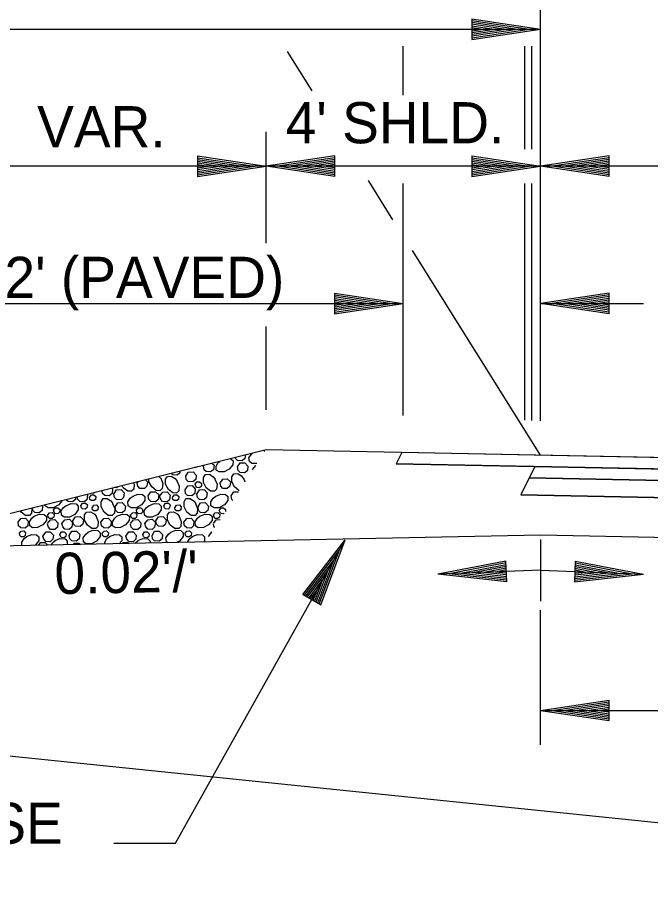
# Model space of a CAD drawing. Extents: x 2478 to 3210, y 439 to 841.
# Drawn here: x 2590.31 to 2608.74, y 577.82 to 603.61 of the extents above; entities that cross this region are included whole.
import ezdxf

# ---------------------------------------------------------------- set-up
doc = ezdxf.new("R2010")
doc.units = 0
for name, color, linetype in [('19', 7, 'Continuous'), ('R_Annotation', 7, 'Continuous'), ('R_Dimension', 7, 'Continuous'), ('R_Exist Surface', 7, 'Continuous')]:
    doc.layers.add(name, color=color, linetype=linetype)

msp = doc.modelspace()

# ---------------------------------------------------------------- linework, layer by layer
at = {"layer": '19'}
for points in [[(2601.503, 590.935), (2601.338, 590.605), (2605.378, 590.524), (2627.711, 590.078), (2649.713, 589.634), (2653.713, 589.474), (2653.543, 589.814), (2649.543, 589.974), (2627.543, 590.414)], [(2605.378, 590.524), (2605.212, 590.194), (2649.879, 589.301), (2649.713, 589.634)], [(2605.212, 590.194), (2604.965, 589.699), (2650.132, 588.796), (2649.879, 589.301)]]:
    msp.add_lwpolyline(points, close=True, dxfattribs=at)
at = {"layer": 'R_Annotation'}
for p, q in [((2597.543, 591.014), (2577.543, 586.014)), ((2627.543, 590.414), (2597.543, 591.014)), ((2601.503, 590.935), (2601.338, 590.605)), ((2627.711, 590.078), (2601.338, 590.605)), ((2605.378, 590.524), (2604.965, 589.699)), ((2627.879, 589.741), (2605.212, 590.194)), ((2628.132, 589.236), (2604.965, 589.699)), ((2605.543, 588.52), (2586.003, 588.129)), ((2666.995, 587.291), (2605.543, 588.52))]:
    msp.add_line(p, q, dxfattribs=at)
at = {"layer": 'R_Dimension'}
for p, q in [((2605.543, 599.281), (2605.543, 604.281)), ((2603.543, 603.581), (2605.543, 603.281)), ((2603.543, 603.581), (2603.543, 602.981)), ((2603.543, 603.531), (2605.209, 603.281)), ((2603.543, 603.48), (2604.865, 603.281)), ((2603.543, 603.43), (2604.532, 603.281)), ((2603.543, 603.378), (2604.193, 603.281)), ((2577.543, 603.281), (2605.543, 603.281)), ((2603.543, 603.328), (2603.859, 603.281)), ((2603.543, 602.981), (2605.543, 603.281)), ((2603.543, 603.183), (2604.193, 603.281)), ((2603.543, 603.082), (2604.865, 603.281)), ((2603.543, 603.031), (2605.209, 603.281)), ((2603.543, 603.132), (2604.532, 603.281)), ((2603.543, 603.234), (2603.859, 603.281)), ((2598.891, 601.477), (2598.169, 602.629)), ((2601.539, 601.351), (2601.539, 602.781)), ((2605.08, 599.781), (2605.08, 602.781)), ((2605.29, 599.781), (2605.29, 602.781)), ((2597.543, 597.038), (2597.543, 600.281)), ((2595.543, 599.581), (2597.543, 599.281)), ((2595.543, 599.581), (2595.543, 598.981)), ((2595.543, 599.531), (2597.209, 599.281)), ((2595.543, 599.48), (2596.865, 599.281)), ((2599.543, 599.581), (2597.543, 599.281)), ((2599.543, 599.531), (2597.877, 599.281)), ((2599.543, 599.48), (2598.221, 599.281)), ((2599.543, 598.981), (2599.543, 599.581)), ((2603.543, 599.581), (2605.543, 599.281)), ((2603.543, 599.581), (2603.543, 598.981)), ((2603.543, 599.531), (2605.209, 599.281)), ((2603.543, 599.48), (2604.865, 599.281)), ((2607.543, 599.581), (2605.543, 599.281)), ((2607.543, 599.531), (2605.877, 599.281)), ((2607.543, 599.48), (2606.221, 599.281)), ((2607.543, 598.981), (2607.543, 599.581)), ((2666.995, 599.281), (2586.003, 599.281)), ((2595.543, 599.43), (2596.532, 599.281)), ((2595.543, 599.378), (2596.193, 599.281)), ((2595.543, 599.328), (2595.859, 599.281)), ((2595.543, 598.981), (2597.543, 599.281)), ((2595.543, 599.183), (2596.193, 599.281)), ((2595.543, 599.082), (2596.865, 599.281)), ((2595.543, 599.031), (2597.209, 599.281)), ((2595.543, 599.132), (2596.532, 599.281)), ((2595.543, 599.234), (2595.859, 599.281)), ((2599.543, 598.981), (2597.543, 599.281)), ((2599.543, 599.031), (2597.877, 599.281)), ((2599.543, 599.082), (2598.221, 599.281)), ((2599.543, 599.43), (2598.554, 599.281)), ((2599.543, 599.132), (2598.554, 599.281)), ((2599.543, 599.379), (2598.893, 599.281)), ((2599.543, 599.184), (2598.893, 599.281)), ((2599.543, 599.328), (2599.227, 599.281)), ((2599.543, 599.234), (2599.227, 599.281)), ((2603.543, 599.43), (2604.532, 599.281)), ((2603.543, 599.378), (2604.193, 599.281)), ((2603.543, 599.328), (2603.859, 599.281)), ((2603.543, 598.981), (2605.543, 599.281)), ((2603.543, 599.183), (2604.193, 599.281)), ((2603.543, 599.082), (2604.865, 599.281)), ((2603.543, 599.031), (2605.209, 599.281)), ((2603.543, 599.132), (2604.532, 599.281)), ((2603.543, 599.234), (2603.859, 599.281)), ((2605.543, 591.855), (2605.543, 599.281)), ((2607.543, 598.981), (2605.543, 599.281)), ((2607.543, 599.031), (2605.877, 599.281)), ((2607.543, 599.082), (2606.221, 599.281)), ((2607.543, 599.43), (2606.554, 599.281)), ((2607.543, 599.132), (2606.554, 599.281)), ((2607.543, 599.379), (2606.893, 599.281)), ((2607.543, 599.184), (2606.893, 599.281)), ((2607.543, 599.328), (2607.227, 599.281)), ((2607.543, 599.234), (2607.227, 599.281)), ((2601.242, 597.722), (2600.528, 598.862)), ((2601.539, 592.015), (2601.539, 598.781)), ((2605.08, 591.874), (2605.08, 598.781)), ((2605.29, 591.865), (2605.29, 598.781)), ((2605.543, 590.854), (2601.806, 596.822)), ((2599.539, 595.581), (2601.539, 595.281)), ((2599.539, 595.581), (2599.539, 594.981)), ((2599.539, 595.531), (2601.205, 595.281)), ((2599.539, 595.48), (2600.861, 595.281)), ((2599.539, 595.43), (2600.528, 595.281)), ((2599.539, 595.378), (2600.189, 595.281)), ((2607.543, 595.581), (2605.543, 595.281)), ((2607.543, 595.531), (2605.877, 595.281)), ((2607.543, 595.48), (2606.221, 595.281)), ((2607.543, 595.43), (2606.554, 595.281)), ((2607.543, 595.379), (2606.893, 595.281)), ((2607.543, 594.981), (2607.543, 595.581)), ((2588.615, 595.281), (2601.539, 595.281)), ((2599.539, 595.328), (2599.855, 595.281)), ((2599.539, 594.981), (2601.539, 595.281)), ((2599.539, 595.183), (2600.189, 595.281)), ((2599.539, 595.082), (2600.861, 595.281)), ((2599.539, 595.031), (2601.205, 595.281)), ((2599.539, 595.132), (2600.528, 595.281)), ((2599.539, 595.234), (2599.855, 595.281)), ((2607.543, 594.981), (2605.543, 595.281)), ((2605.543, 595.281), (2608.543, 595.281)), ((2607.543, 595.031), (2605.877, 595.281)), ((2607.543, 595.082), (2606.221, 595.281)), ((2607.543, 595.132), (2606.554, 595.281)), ((2607.543, 595.184), (2606.893, 595.281)), ((2607.543, 595.328), (2607.227, 595.281)), ((2607.543, 595.234), (2607.227, 595.281)), ((2597.543, 592.175), (2597.543, 594.607)), ((2597.475, 590.997), (2597.51, 590.965)), ((2595.723, 590.534), (2595.745, 590.565)), ((2594.424, 590.235), (2594.473, 590.174)), ((2596.888, 590.184), (2596.928, 590.08)), ((2597.156, 590.427), (2597.153, 590.439)), ((2593.788, 590.044), (2593.814, 590.082)), ((2595.877, 588.483), (2595.873, 588.494)), ((2598.613, 586.79), (2599.851, 588.389)), ((2599.136, 586.497), (2599.851, 588.389)), ((2605.543, 588.402), (2605.543, 586.604)), ((2598.656, 586.766), (2599.688, 588.098)), ((2599.093, 586.522), (2599.688, 588.098)), ((2598.701, 586.741), (2599.52, 587.798)), ((2599.048, 586.547), (2599.52, 587.798)), ((2604.531, 587.763), (2602.545, 587.383)), ((2604.533, 587.713), (2602.879, 587.396)), ((2604.535, 587.662), (2603.222, 587.41)), ((2604.537, 587.612), (2603.555, 587.423)), ((2604.555, 587.163), (2604.531, 587.763)), ((2606.553, 587.763), (2606.53, 587.163)), ((2606.547, 587.612), (2607.53, 587.424)), ((2606.549, 587.662), (2607.862, 587.41)), ((2606.551, 587.713), (2608.206, 587.397)), ((2606.553, 587.763), (2608.54, 587.383)), ((2598.744, 586.717), (2599.357, 587.507)), ((2599.004, 586.571), (2599.357, 587.507)), ((2605.543, 587.503), (2602.545, 587.383)), ((2604.555, 587.163), (2602.545, 587.383)), ((2604.553, 587.213), (2602.879, 587.396)), ((2604.551, 587.264), (2603.222, 587.41)), ((2604.549, 587.314), (2603.555, 587.423)), ((2604.539, 587.561), (2603.894, 587.437)), ((2604.547, 587.366), (2603.894, 587.437)), ((2604.542, 587.51), (2604.228, 587.45)), ((2604.545, 587.416), (2604.228, 587.45)), ((2605.543, 587.503), (2608.54, 587.383)), ((2606.53, 587.163), (2608.54, 587.383)), ((2606.532, 587.213), (2608.206, 587.397)), ((2606.534, 587.264), (2607.862, 587.41)), ((2606.536, 587.314), (2607.53, 587.424)), ((2606.538, 587.365), (2607.191, 587.437)), ((2606.54, 587.416), (2606.857, 587.45)), ((2606.543, 587.51), (2606.857, 587.45)), ((2606.545, 587.56), (2607.191, 587.437)), ((2598.79, 586.691), (2599.192, 587.211)), ((2598.96, 586.596), (2599.192, 587.211)), ((2598.833, 586.667), (2599.029, 586.92)), ((2598.915, 586.621), (2599.029, 586.92)), ((2598.613, 586.79), (2599.136, 586.497)), ((2605.543, 582.406), (2605.543, 586.336)), ((2607.543, 583.706), (2605.543, 583.406)), ((2607.543, 583.656), (2605.877, 583.406)), ((2607.543, 583.605), (2606.221, 583.406)), ((2607.543, 583.555), (2606.554, 583.406)), ((2607.543, 583.504), (2606.893, 583.406)), ((2607.543, 583.106), (2607.543, 583.706)), ((2607.543, 583.106), (2605.543, 583.406)), ((2649.543, 583.406), (2605.543, 583.406)), ((2607.543, 583.156), (2605.877, 583.406)), ((2607.543, 583.207), (2606.221, 583.406)), ((2607.543, 583.257), (2606.554, 583.406)), ((2607.543, 583.309), (2606.893, 583.406)), ((2607.543, 583.453), (2607.227, 583.406)), ((2607.543, 583.359), (2607.227, 583.406))]:
    msp.add_line(p, q, dxfattribs=at)
for points in [[(2596.506, 590.755), (2596.518, 590.754), (2596.583, 590.689), (2596.578, 590.574), (2596.473, 590.444), (2596.323, 590.369), (2596.173, 590.369), (2596.093, 590.424), (2596.088, 590.539), (2596.153, 590.644), (2596.193, 590.677)], [(2596.94, 590.864), (2596.928, 590.759), (2596.843, 590.694), (2596.713, 590.699), (2596.653, 590.759), (2596.648, 590.791)], [(2597.279, 590.614), (2597.133, 590.614), (2597.058, 590.674), (2597.043, 590.784), (2597.118, 590.889), (2597.145, 590.915)], [(2595.521, 590.509), (2595.493, 590.494), (2595.458, 590.493)], [(2595.968, 590.621), (2596.028, 590.564), (2596.013, 590.434), (2595.928, 590.369), (2595.803, 590.379), (2595.743, 590.434), (2595.723, 590.534)], [(2596.713, 590.514), (2596.793, 590.629), (2596.923, 590.634), (2597.013, 590.539), (2597.003, 590.409), (2596.923, 590.339), (2596.793, 590.354), (2596.733, 590.414), (2596.713, 590.514)], [(2597.153, 590.439), (2597.243, 590.559), (2597.243, 590.559)], [(2594.473, 590.184), (2594.533, 590.029), (2594.518, 589.889), (2594.453, 589.819), (2594.338, 589.829), (2594.213, 589.929), (2594.128, 590.084), (2594.128, 590.161)], [(2594.948, 590.109), (2595.008, 589.954), (2594.998, 589.814), (2594.938, 589.749), (2594.823, 589.754), (2594.698, 589.854), (2594.613, 590.009), (2594.613, 590.154), (2594.668, 590.234), (2594.783, 590.249), (2594.893, 590.174), (2594.953, 590.099)], [(2595.036, 590.388), (2595.033, 590.339), (2594.953, 590.274), (2594.823, 590.279), (2594.779, 590.323)], [(2595.203, 590.249), (2595.278, 590.359), (2595.418, 590.369), (2595.503, 590.274), (2595.493, 590.144), (2595.408, 590.079), (2595.278, 590.089), (2595.218, 590.144), (2595.203, 590.249)], [(2596.053, 590.159), (2596.118, 590.009), (2596.103, 589.869), (2596.038, 589.804), (2595.928, 589.809), (2595.798, 589.904), (2595.723, 590.059), (2595.718, 590.209), (2595.783, 590.294), (2595.893, 590.299), (2596.003, 590.229), (2596.063, 590.154)], [(2596.762, 589.829), (2596.753, 589.829), (2596.628, 589.929), (2596.543, 590.084), (2596.543, 590.229), (2596.603, 590.314), (2596.723, 590.319), (2596.823, 590.254), (2596.888, 590.174)], [(2593.227, 589.936), (2593.193, 589.904), (2593.133, 589.912)], [(2593.685, 590.05), (2593.703, 590.009), (2593.688, 589.869), (2593.623, 589.804), (2593.513, 589.809), (2593.383, 589.904), (2593.352, 589.967)], [(2594.032, 590.137), (2594.093, 590.079), (2594.073, 589.949), (2593.998, 589.884), (2593.868, 589.889), (2593.808, 589.949), (2593.788, 590.044)], [(2595.183, 589.844), (2595.263, 589.964), (2595.388, 589.969), (2595.483, 589.869), (2595.473, 589.744), (2595.383, 589.674), (2595.258, 589.679), (2595.198, 589.744), (2595.183, 589.844)], [(2595.483, 590.009), (2595.528, 590.079), (2595.608, 590.084), (2595.663, 590.029), (2595.658, 589.949), (2595.608, 589.904), (2595.528, 589.914), (2595.493, 589.949), (2595.483, 590.009)], [(2596.203, 590.044), (2596.283, 590.159), (2596.413, 590.169), (2596.508, 590.079), (2596.488, 589.949), (2596.413, 589.884), (2596.283, 589.889), (2596.223, 589.949), (2596.203, 590.044)], [(2592.323, 589.709), (2592.338, 589.694), (2592.318, 589.559), (2592.243, 589.494), (2592.113, 589.504), (2592.058, 589.564), (2592.036, 589.638)], [(2592.403, 589.624), (2592.458, 589.699), (2592.528, 589.699), (2592.583, 589.649), (2592.578, 589.564), (2592.528, 589.534), (2592.448, 589.539), (2592.413, 589.564), (2592.403, 589.624)], [(2592.535, 589.762), (2592.523, 589.749), (2592.489, 589.751)], [(2593.047, 589.891), (2593.068, 589.869), (2593.058, 589.744), (2592.968, 589.674), (2592.843, 589.679), (2592.783, 589.744), (2592.771, 589.821)], [(2593.108, 589.724), (2593.188, 589.844), (2593.323, 589.854), (2593.408, 589.754), (2593.393, 589.624), (2593.318, 589.559), (2593.188, 589.564), (2593.128, 589.624), (2593.108, 589.724)], [(2593.663, 589.659), (2593.813, 589.719), (2593.948, 589.709), (2594.013, 589.649), (2594.013, 589.534), (2593.918, 589.404), (2593.758, 589.324), (2593.613, 589.324), (2593.523, 589.379), (2593.518, 589.494), (2593.588, 589.604), (2593.668, 589.664)], [(2594.113, 589.669), (2594.188, 589.784), (2594.323, 589.789), (2594.418, 589.699), (2594.403, 589.564), (2594.318, 589.499), (2594.188, 589.509), (2594.128, 589.564), (2594.113, 589.669)], [(2594.443, 589.664), (2594.533, 589.779), (2594.658, 589.789), (2594.753, 589.694), (2594.733, 589.559), (2594.658, 589.494), (2594.528, 589.504), (2594.473, 589.564), (2594.443, 589.664)], [(2594.818, 589.624), (2594.873, 589.699), (2594.943, 589.699), (2594.998, 589.649), (2594.993, 589.564), (2594.943, 589.534), (2594.863, 589.539), (2594.828, 589.564), (2594.818, 589.624)], [(2595.523, 589.724), (2595.603, 589.844), (2595.738, 589.854), (2595.823, 589.754), (2595.808, 589.624), (2595.733, 589.559), (2595.603, 589.564), (2595.543, 589.624), (2595.523, 589.724)], [(2596.078, 589.659), (2596.228, 589.719), (2596.363, 589.709), (2596.428, 589.649), (2596.428, 589.534), (2596.333, 589.404), (2596.173, 589.324), (2596.028, 589.324), (2595.938, 589.379), (2595.933, 589.494), (2596.003, 589.604), (2596.083, 589.664)], [(2596.528, 589.669), (2596.603, 589.784), (2596.736, 589.789)], [(2596.571, 589.538), (2596.543, 589.564), (2596.528, 589.669)], [(2591.592, 589.527), (2591.503, 589.404), (2591.343, 589.324), (2591.198, 589.324), (2591.108, 589.379), (2591.106, 589.405)], [(2591.713, 589.384), (2591.868, 589.444), (2592.008, 589.434), (2592.073, 589.374), (2592.073, 589.259), (2591.973, 589.129), (2591.813, 589.054), (2591.663, 589.049), (2591.583, 589.109), (2591.578, 589.229), (2591.643, 589.329), (2591.723, 589.389)], [(2591.995, 589.627), (2591.988, 589.564), (2591.903, 589.499), (2591.773, 589.509), (2591.719, 589.558)], [(2592.148, 589.384), (2592.198, 589.454), (2592.283, 589.454), (2592.338, 589.404), (2592.318, 589.324), (2592.273, 589.284), (2592.198, 589.289), (2592.168, 589.324), (2592.148, 589.384)], [(2593.073, 589.449), (2593.133, 589.304), (2593.123, 589.164), (2593.063, 589.094), (2592.948, 589.094), (2592.823, 589.199), (2592.738, 589.354), (2592.738, 589.499), (2592.793, 589.589), (2592.913, 589.594), (2593.018, 589.529), (2593.078, 589.444)], [(2593.148, 589.349), (2593.223, 589.464), (2593.353, 589.474), (2593.448, 589.374), (2593.433, 589.244), (2593.348, 589.179), (2593.223, 589.184), (2593.163, 589.244), (2593.148, 589.349)], [(2594.128, 589.384), (2594.283, 589.444), (2594.423, 589.434), (2594.488, 589.374), (2594.488, 589.259), (2594.388, 589.129), (2594.228, 589.054), (2594.078, 589.049), (2593.998, 589.109), (2593.993, 589.229), (2594.058, 589.329), (2594.138, 589.389)], [(2594.563, 589.384), (2594.613, 589.454), (2594.698, 589.454), (2594.753, 589.404), (2594.733, 589.324), (2594.688, 589.284), (2594.613, 589.289), (2594.583, 589.324), (2594.563, 589.384)], [(2595.488, 589.449), (2595.548, 589.304), (2595.538, 589.164), (2595.478, 589.094), (2595.363, 589.094), (2595.238, 589.199), (2595.153, 589.354), (2595.153, 589.499), (2595.208, 589.589), (2595.328, 589.594), (2595.433, 589.529), (2595.493, 589.444)], [(2595.563, 589.349), (2595.638, 589.464), (2595.768, 589.474), (2595.863, 589.374), (2595.848, 589.244), (2595.763, 589.179), (2595.638, 589.184), (2595.578, 589.244), (2595.563, 589.349)], [(2590.716, 589.308), (2590.718, 589.304), (2590.708, 589.164), (2590.648, 589.094), (2590.533, 589.094), (2590.408, 589.199), (2590.393, 589.227)], [(2591.023, 589.384), (2591.033, 589.374), (2591.018, 589.244), (2590.933, 589.179), (2590.808, 589.184), (2590.748, 589.244), (2590.738, 589.313)], [(2591.183, 589.114), (2591.233, 589.179), (2591.313, 589.184), (2591.368, 589.129), (2591.358, 589.049), (2591.313, 589.009), (2591.233, 589.014), (2591.198, 589.054), (2591.183, 589.114)], [(2591.353, 589.254), (2591.403, 589.319), (2591.478, 589.324), (2591.533, 589.269), (2591.528, 589.194), (2591.478, 589.149), (2591.403, 589.159), (2591.368, 589.194), (2591.353, 589.254)], [(2592.593, 589.069), (2592.653, 588.924), (2592.643, 588.779), (2592.583, 588.714), (2592.468, 588.714), (2592.338, 588.819), (2592.258, 588.964), (2592.253, 589.119), (2592.313, 589.199), (2592.428, 589.209), (2592.538, 589.144), (2592.603, 589.064)], [(2592.473, 589.324), (2592.523, 589.399), (2592.603, 589.404), (2592.653, 589.349), (2592.643, 589.264), (2592.593, 589.229), (2592.523, 589.234), (2592.483, 589.264), (2592.473, 589.324)], [(2593.598, 589.114), (2593.648, 589.179), (2593.728, 589.184), (2593.783, 589.129), (2593.773, 589.049), (2593.728, 589.009), (2593.648, 589.014), (2593.613, 589.054), (2593.598, 589.114)], [(2593.768, 589.254), (2593.818, 589.319), (2593.893, 589.324), (2593.948, 589.269), (2593.943, 589.194), (2593.893, 589.149), (2593.818, 589.159), (2593.783, 589.194), (2593.768, 589.254)], [(2595.008, 589.069), (2595.068, 588.924), (2595.058, 588.779), (2594.998, 588.714), (2594.883, 588.714), (2594.753, 588.819), (2594.673, 588.964), (2594.668, 589.119), (2594.728, 589.199), (2594.843, 589.209), (2594.953, 589.144), (2595.018, 589.064)], [(2594.888, 589.324), (2594.938, 589.399), (2595.018, 589.404), (2595.068, 589.349), (2595.058, 589.264), (2595.008, 589.229), (2594.938, 589.234), (2594.898, 589.264), (2594.888, 589.324)], [(2596.013, 589.114), (2596.063, 589.179), (2596.143, 589.184), (2596.198, 589.129), (2596.188, 589.049), (2596.143, 589.009), (2596.063, 589.014), (2596.028, 589.054), (2596.013, 589.114)], [(2596.183, 589.254), (2596.233, 589.319), (2596.308, 589.324), (2596.363, 589.269), (2596.359, 589.216)], [(2596.327, 589.166), (2596.308, 589.149), (2596.233, 589.159), (2596.198, 589.194), (2596.183, 589.254)], [(2590.318, 588.899), (2590.403, 589.014), (2590.533, 589.019), (2590.613, 588.929), (2590.603, 588.799), (2590.528, 588.729), (2590.403, 588.739), (2590.333, 588.799), (2590.318, 588.899)], [(2590.783, 589.074), (2590.933, 589.134), (2591.078, 589.124), (2591.148, 589.064), (2591.143, 588.949), (2591.038, 588.824), (2590.888, 588.744), (2590.738, 588.739), (2590.658, 588.799), (2590.653, 588.914), (2590.718, 589.019), (2590.793, 589.084)], [(2591.178, 588.864), (2591.263, 588.974), (2591.393, 588.984), (2591.478, 588.884), (2591.468, 588.759), (2591.393, 588.689), (2591.263, 588.694), (2591.203, 588.759), (2591.178, 588.849)], [(2591.598, 588.864), (2591.683, 588.974), (2591.813, 588.989), (2591.903, 588.889), (2591.883, 588.759), (2591.808, 588.694), (2591.683, 588.704), (2591.623, 588.764), (2591.598, 588.864)], [(2591.918, 588.944), (2591.993, 589.059), (2592.128, 589.069), (2592.223, 588.974), (2592.203, 588.844), (2592.123, 588.779), (2591.993, 588.784), (2591.933, 588.844), (2591.918, 588.944)], [(2592.733, 588.899), (2592.818, 589.014), (2592.948, 589.019), (2593.028, 588.929), (2593.018, 588.799), (2592.943, 588.729), (2592.818, 588.739), (2592.748, 588.799), (2592.733, 588.899)], [(2593.198, 589.074), (2593.348, 589.134), (2593.493, 589.124), (2593.563, 589.064), (2593.558, 588.949), (2593.453, 588.824), (2593.303, 588.744), (2593.153, 588.739), (2593.073, 588.799), (2593.068, 588.914), (2593.133, 589.019), (2593.208, 589.084)], [(2593.593, 588.864), (2593.678, 588.974), (2593.808, 588.984), (2593.893, 588.884), (2593.883, 588.759), (2593.808, 588.689), (2593.678, 588.694), (2593.618, 588.759), (2593.593, 588.849)], [(2594.013, 588.864), (2594.098, 588.974), (2594.228, 588.989), (2594.318, 588.889), (2594.298, 588.759), (2594.223, 588.694), (2594.098, 588.704), (2594.038, 588.764), (2594.013, 588.864)], [(2594.333, 588.944), (2594.408, 589.059), (2594.543, 589.069), (2594.638, 588.974), (2594.618, 588.844), (2594.538, 588.779), (2594.408, 588.784), (2594.348, 588.844), (2594.333, 588.944)], [(2595.148, 588.899), (2595.233, 589.014), (2595.363, 589.019), (2595.443, 588.929), (2595.433, 588.799), (2595.358, 588.729), (2595.233, 588.739), (2595.163, 588.799), (2595.148, 588.899)], [(2595.613, 589.074), (2595.763, 589.134), (2595.908, 589.124), (2595.978, 589.064), (2595.973, 588.949), (2595.868, 588.824), (2595.718, 588.744), (2595.568, 588.739), (2595.488, 588.799), (2595.483, 588.914), (2595.548, 589.019), (2595.623, 589.084)], [(2596.008, 588.864), (2596.093, 588.974), (2596.206, 588.983)], [(2590.358, 588.579), (2590.408, 588.644), (2590.483, 588.649), (2590.538, 588.594), (2590.528, 588.519), (2590.483, 588.474), (2590.408, 588.479), (2590.368, 588.519), (2590.358, 588.579)], [(2591.808, 588.519), (2591.883, 588.639), (2592.018, 588.644), (2592.113, 588.544), (2592.098, 588.419), (2592.013, 588.354), (2591.883, 588.359), (2591.823, 588.419), (2591.808, 588.519)], [(2592.353, 588.614), (2592.503, 588.674), (2592.643, 588.659), (2592.713, 588.594), (2592.713, 588.484), (2592.608, 588.354), (2592.458, 588.274), (2592.303, 588.274), (2592.228, 588.334), (2592.213, 588.444), (2592.288, 588.549), (2592.358, 588.614)], [(2592.773, 588.579), (2592.823, 588.644), (2592.898, 588.649), (2592.953, 588.594), (2592.943, 588.519), (2592.898, 588.474), (2592.823, 588.479), (2592.783, 588.519), (2592.773, 588.579)], [(2594.223, 588.519), (2594.298, 588.639), (2594.433, 588.644), (2594.528, 588.544), (2594.513, 588.419), (2594.428, 588.354), (2594.298, 588.359), (2594.238, 588.419), (2594.223, 588.519)], [(2594.768, 588.614), (2594.918, 588.674), (2595.058, 588.659), (2595.128, 588.594), (2595.128, 588.484), (2595.023, 588.354), (2594.936, 588.308)], [(2595.188, 588.579), (2595.238, 588.644), (2595.313, 588.649), (2595.368, 588.594), (2595.358, 588.519), (2595.313, 588.474), (2595.238, 588.479), (2595.198, 588.519), (2595.188, 588.579)], [(2596.048, 588.743), (2596.033, 588.759), (2596.008, 588.849)], [(2590.432, 588.218), (2590.428, 588.319), (2590.493, 588.429), (2590.573, 588.489)], [(2590.563, 588.484), (2590.718, 588.544), (2590.858, 588.534), (2590.923, 588.474), (2590.923, 588.359), (2590.818, 588.234), (2590.8, 588.225)], [(2591.043, 588.494), (2591.133, 588.619), (2591.258, 588.624), (2591.348, 588.529), (2591.333, 588.404), (2591.258, 588.334), (2591.128, 588.344), (2591.073, 588.404), (2591.043, 588.494)], [(2591.393, 588.364), (2591.543, 588.424), (2591.688, 588.414), (2591.753, 588.349), (2591.748, 588.244)], [(2591.538, 588.544), (2591.588, 588.619), (2591.663, 588.624), (2591.723, 588.564), (2591.713, 588.484), (2591.663, 588.444), (2591.588, 588.459), (2591.553, 588.484), (2591.538, 588.544)], [(2592.845, 588.266), (2592.843, 588.319), (2592.908, 588.429), (2592.988, 588.489)], [(2592.978, 588.484), (2593.133, 588.544), (2593.273, 588.534), (2593.338, 588.474), (2593.338, 588.359), (2593.266, 588.275)], [(2593.105, 579.543), (2594.903, 579.543), (2599.851, 588.389)], [(2593.458, 588.494), (2593.548, 588.619), (2593.673, 588.624), (2593.763, 588.529), (2593.748, 588.404), (2593.673, 588.334), (2593.543, 588.344), (2593.488, 588.404), (2593.458, 588.494)], [(2593.808, 588.364), (2593.958, 588.424), (2594.103, 588.414), (2594.168, 588.349), (2594.165, 588.293)], [(2593.953, 588.544), (2594.003, 588.619), (2594.078, 588.624), (2594.138, 588.564), (2594.128, 588.484), (2594.078, 588.444), (2594.003, 588.459), (2593.968, 588.484), (2593.953, 588.544)], [(2594.682, 588.303), (2594.643, 588.334), (2594.628, 588.444), (2594.703, 588.549), (2594.773, 588.614)], [(2595.258, 588.315), (2595.258, 588.319), (2595.323, 588.429), (2595.403, 588.489)], [(2595.393, 588.484), (2595.548, 588.544), (2595.688, 588.534), (2595.753, 588.474), (2595.753, 588.359), (2595.723, 588.324)], [(2595.873, 588.494), (2595.963, 588.619), (2595.967, 588.62)], [(2590.917, 588.228), (2590.978, 588.309), (2591.103, 588.314), (2591.188, 588.233)], [(2591.28, 588.235), (2591.323, 588.304), (2591.398, 588.364)], [(2591.934, 588.248), (2591.963, 588.289), (2592.093, 588.294), (2592.133, 588.252)], [(2593.368, 588.277), (2593.393, 588.309), (2593.518, 588.314), (2593.553, 588.28)], [(2593.725, 588.284), (2593.738, 588.304), (2593.813, 588.364)]]:
    msp.add_lwpolyline(points, dxfattribs=at)
at = {"layer": 'R_Exist Surface'}
msp.add_lwpolyline([(2559.048, 580.013), (2580.798, 583.038), (2610.269, 580.01), (2642.749, 581.692), (2680.214, 577.819), (2705.082, 582.167)], dxfattribs=at)

# ---------------------------------------------------------------- texts
at = {"layer": 'R_Annotation'}
for s, p in [('VAR.', (2590.874, 599.834)), ("4' SHLD.", (2598.115, 599.951)), ("2' (PAVED)", (2589.921, 595.442)), ('AGGREGATE BASE COURSE', (2569.419, 579.524))]:
    msp.add_text(s, height=1.2, dxfattribs=at).set_placement(p)
msp.add_text("0.02'/'", height=1.2, rotation=1.0613, dxfattribs=at).set_placement((2591.389, 586.804))

doc.saveas('drawing.dxf')
